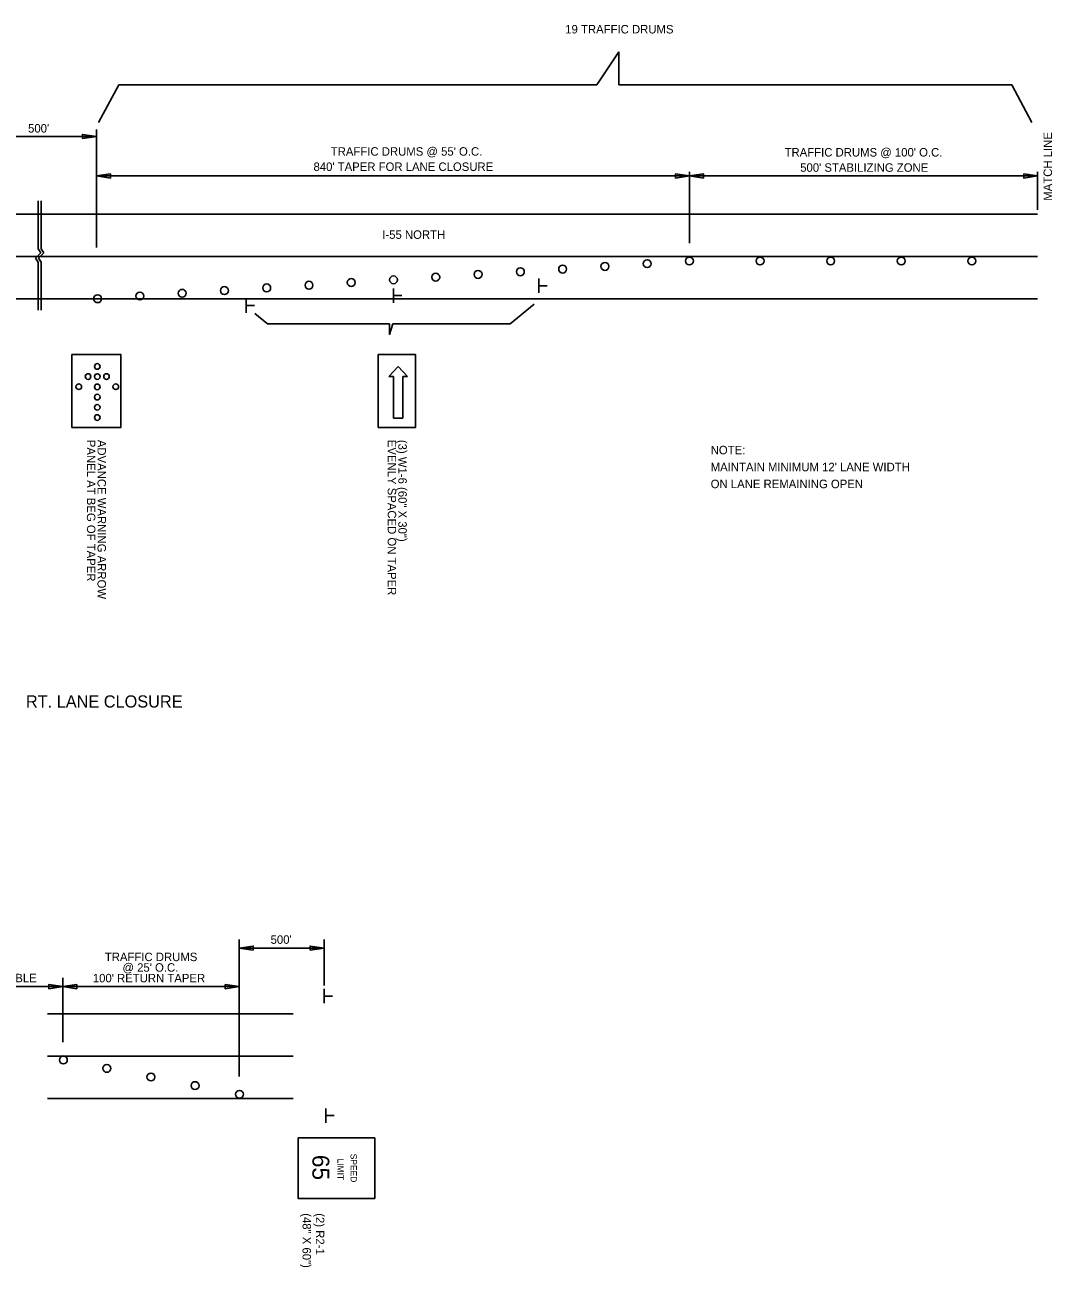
# Model space of a CAD drawing. Extents: x -900 to -62, y -12423 to -11428.
# Drawn here: x -370.1 to -79.1, y -11779.7 to -11427.8 of the extents above; entities that cross this region are included whole.
import ezdxf

# ---------------------------------------------------------------- set-up
doc = ezdxf.new("R2010")
doc.units = 0
doc.layers.add('1', color=7, linetype='Continuous')
doc.layers.add('R_MOT', color=7, linetype='Continuous')

msp = doc.modelspace()

# ---------------------------------------------------------------- linework, layer by layer
at = {"layer": '1'}
for p, q in [((-201.79, -11435.42), (-208.06, -11444.82)), ((-201.79, -11444.82), (-201.79, -11435.42)), ((-349.18, -11455.47), (-343.48, -11444.82)), ((-208.06, -11444.82), (-343.48, -11444.82)), ((-90.51, -11444.82), (-201.79, -11444.82)), ((-84.81, -11455.47), (-90.51, -11444.82)), ((-349.8, -11457.44), (-349.8, -11490.86)), ((-349.8, -11459.44), (-382.15, -11459.44)), ((-181.8, -11470.61), (-349.8, -11470.61)), ((-181.8, -11489.66), (-181.8, -11469.41)), ((-181.8, -11470.61), (-83.17, -11470.61)), ((-83.17, -11480.2), (-83.17, -11469.41)), ((-366.34, -11477.63), (-366.34, -11491.23)), ((-365.47, -11477.63), (-365.47, -11491.23)), ((-682.04, -11481.4), (-83.17, -11481.4)), ((-367.1, -11493.91), (-365.57, -11492.38)), ((-365.57, -11492.38), (-366.34, -11491.23)), ((-366.23, -11493.91), (-364.7, -11492.38)), ((-364.7, -11492.38), (-365.47, -11491.23)), ((-682.04, -11493.4), (-83.17, -11493.4)), ((-366.34, -11495.06), (-367.1, -11493.91)), ((-366.34, -11495.06), (-366.34, -11508.66)), ((-365.47, -11495.06), (-366.23, -11493.91)), ((-365.47, -11495.06), (-365.47, -11508.66)), ((-224.48, -11499.69), (-224.48, -11503.76)), ((-265.66, -11502.47), (-265.66, -11506.54)), ((-224.48, -11501.72), (-222.11, -11501.72)), ((-682.04, -11505.4), (-83.17, -11505.4)), ((-307.39, -11505.3), (-307.39, -11509.37)), ((-265.66, -11504.5), (-263.29, -11504.5)), ((-307.39, -11507.33), (-305.03, -11507.33)), ((-309.36, -11725.66), (-309.36, -11686.88)), ((-285.33, -11689.36), (-309.36, -11689.36)), ((-285.33, -11699.93), (-285.33, -11686.88)), ((-359.36, -11700.25), (-409.93, -11700.25)), ((-359.36, -11715.98), (-359.36, -11697.78)), ((-309.36, -11700.25), (-359.36, -11700.25)), ((-285.27, -11700.87), (-285.27, -11704.94)), ((-285.27, -11702.91), (-282.91, -11702.91)), ((-363.68, -11707.93), (-294.06, -11707.93)), ((-363.68, -11719.93), (-294.06, -11719.93)), ((-363.68, -11731.93), (-294.06, -11731.93)), ((-284.82, -11734.74), (-284.82, -11738.81)), ((-284.82, -11736.77), (-282.45, -11736.77))]:
    msp.add_line(p, q, dxfattribs=at)
for points in [[(-353.76, -11460.04), (-349.8, -11459.44), (-353.76, -11458.84)], [(-345.84, -11471.21), (-349.8, -11470.61), (-345.84, -11470.01)], [(-185.76, -11470.01), (-181.8, -11470.61), (-185.76, -11471.21)], [(-177.84, -11471.21), (-181.8, -11470.61), (-177.84, -11470.01)], [(-87.13, -11470.01), (-83.17, -11470.61), (-87.13, -11471.21)], [(-305.4, -11689.96), (-309.36, -11689.36), (-305.4, -11688.76)], [(-289.29, -11689.96), (-285.33, -11689.36), (-289.29, -11688.76)], [(-363.32, -11700.85), (-359.36, -11700.25), (-363.32, -11699.65)], [(-355.4, -11700.85), (-359.36, -11700.25), (-355.4, -11699.65)], [(-313.32, -11700.85), (-309.36, -11700.25), (-313.32, -11699.65)]]:
    msp.add_lwpolyline(points, close=True, dxfattribs=at)
for points in [[(-265.84, -11512.51), (-232.6, -11512.51), (-225.79, -11506.92)], [(-304.9, -11509.57), (-301.32, -11512.51), (-266.74, -11512.51)], [(-266.74, -11512.51), (-266.74, -11515.48), (-265.84, -11512.51)]]:
    msp.add_lwpolyline(points, dxfattribs=at)
for centre, radius in [((-217.74, -11496.99), 1.12), ((-205.76, -11496.23), 1.12), ((-193.79, -11495.46), 1.12), ((-181.81, -11494.7), 1.12), ((-161.81, -11494.7), 1.12), ((-141.81, -11494.7), 1.12), ((-121.81, -11494.7), 1.12), ((-101.81, -11494.7), 1.12), ((-277.62, -11500.8), 1.12), ((-265.64, -11500.04), 1.12), ((-253.67, -11499.28), 1.12), ((-241.69, -11498.51), 1.12), ((-229.71, -11497.75), 1.12), ((-337.5, -11504.62), 1.12), ((-325.52, -11503.85), 1.12), ((-313.55, -11503.09), 1.12), ((-301.57, -11502.33), 1.12), ((-289.59, -11501.57), 1.12), ((-349.47, -11505.38), 1.12), ((-349.57, -11524.57), 0.796), ((-352.18, -11527.44), 0.796), ((-349.57, -11527.46), 0.796), ((-346.95, -11527.44), 0.796), ((-354.8, -11530.31), 0.796), ((-349.57, -11530.36), 0.796), ((-344.33, -11530.31), 0.796), ((-349.57, -11533.25), 0.796), ((-349.57, -11536.15), 0.796), ((-349.57, -11539.05), 0.796), ((-359.17, -11721), 1.12), ((-346.86, -11723.4), 1.12), ((-334.36, -11725.85), 1.12), ((-321.86, -11728.29), 1.12), ((-309.28, -11730.75), 1.12)]:
    msp.add_circle(centre, radius, dxfattribs=at)
at = {"layer": 'R_MOT'}
for p, q in [((-266.96, -11527.45), (-264.34, -11524.58)), ((-264.34, -11524.58), (-261.72, -11527.45)), ((-265.65, -11527.45), (-266.96, -11527.45)), ((-265.65, -11539.2), (-265.65, -11527.45)), ((-263.03, -11539.2), (-263.03, -11527.45)), ((-263.03, -11527.45), (-261.72, -11527.45)), ((-265.65, -11539.2), (-263.03, -11539.2))]:
    msp.add_line(p, q, dxfattribs=at)
for points in [[(-356.75, -11521.22), (-356.75, -11541.83), (-342.89, -11541.83), (-342.89, -11521.22)], [(-269.96, -11521.22), (-269.96, -11541.83), (-259.41, -11541.83), (-259.41, -11521.22)], [(-270.95, -11760.28), (-292.62, -11760.28), (-292.62, -11743.09), (-270.95, -11743.09)]]:
    msp.add_lwpolyline(points, close=True, dxfattribs=at)

# ---------------------------------------------------------------- texts
at = {"layer": '1'}
for s, height, p in [('19 TRAFFIC DRUMS', 2.4, (-217, -11430.25)), ("500'", 2.4, (-369.17, -11458.32)), ("TRAFFIC DRUMS @ 55' O.C.", 2.4, (-283.42, -11464.87)), ("TRAFFIC DRUMS @ 100' O.C.", 2.4, (-154.86, -11465.11)), ("840' TAPER FOR LANE CLOSURE", 2.4, (-288.31, -11469.19)), ("500' STABILIZING ZONE", 2.4, (-150.44, -11469.43)), ('I-55 NORTH', 2.4, (-268.84, -11488.43)), ('RT. LANE CLOSURE', 3.452, (-369.78, -11621.19))]:
    msp.add_text(s, height=height, dxfattribs=at).set_placement(p)
msp.add_text('MATCH LINE', height=2.4, rotation=90, dxfattribs=at).set_placement((-79.1, -11477.63))
at = {"layer": 'R_MOT'}
for s, height, rotation, p in [('PANEL AT BEG OF TAPER', 2.4, 270, (-352.5, -11545.36)), ('ADVANCE WARNING ARROW', 2.4, 270, (-349.5, -11545.36)), ('EVENLY SPACED ON TAPER', 2.4, 270, (-267.3, -11545.36)), ('(3) W1-6 (60" X 30")', 2.4, 270, (-264.29, -11545.36)), ('NOTE:', 2.4, 360, (-175.8, -11549.46)), ("MAINTAIN MINIMUM 12' LANE WIDTH", 2.4, 360, (-175.8, -11554.26)), ('ON LANE REMAINING OPEN', 2.4, 360, (-175.8, -11559.05)), ("500'", 2.4, 360, (-300.46, -11688.12)), ('TRAFFIC DRUMS', 2.4, 360, (-347.42, -11693.02)), ("@ 25' O.C.", 2.4, 360, (-342.43, -11696.02)), ('WORK ZONE VARIABLE', 2.4, 360, (-403.1, -11699.01)), ("100' RETURN TAPER", 2.4, 360, (-350.83, -11699.03)), ('65', 4.799, 270, (-288.63, -11747.9)), ('LIMIT', 1.791, 270, (-281.52, -11748.94)), ('SPEED', 1.791, 270, (-277.82, -11747.57)), ('(48" X 60")', 2.3996, 270, (-291.42, -11764.43)), ('(2) R2-1', 2.4, 270, (-287.64, -11764.43))]:
    msp.add_text(s, height=height, rotation=rotation, dxfattribs=at).set_placement(p)

doc.saveas('drawing.dxf')
